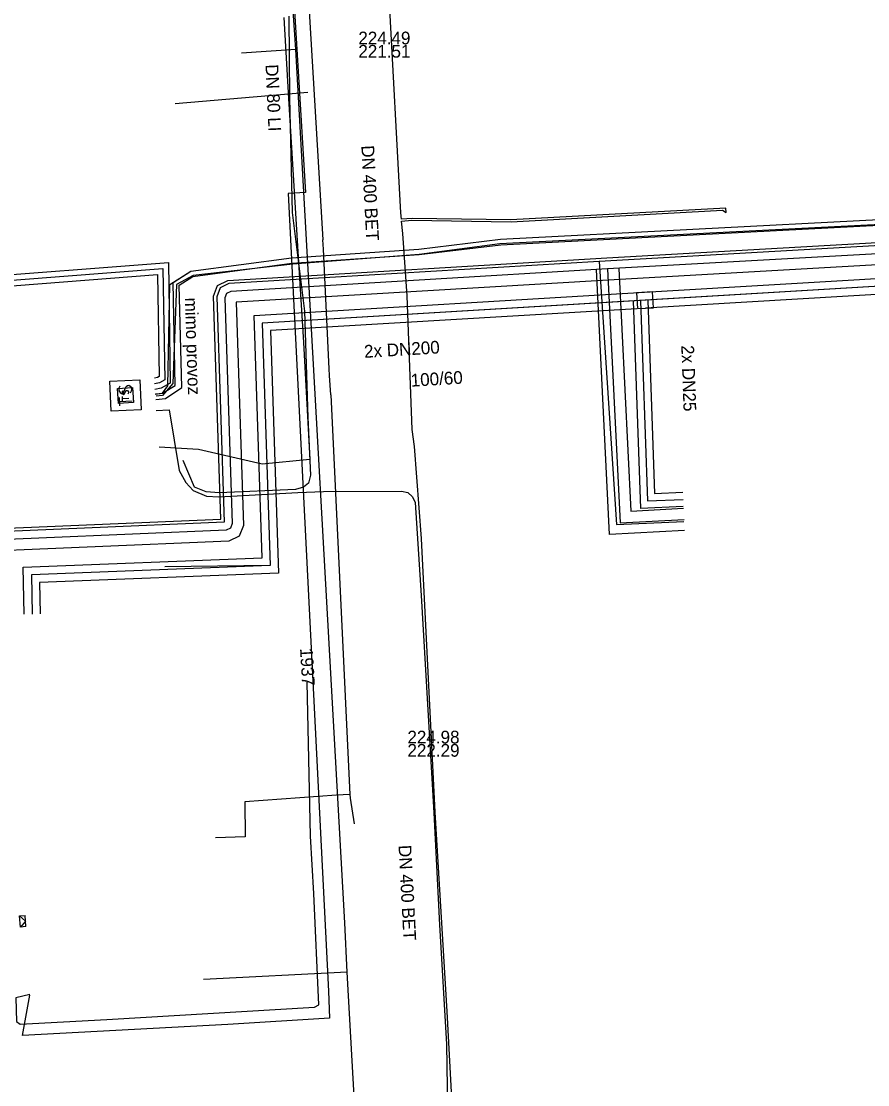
# Model space of a CAD drawing. Extents: x -599951 to -598963, y -1164095 to -1162939.
# Drawn here: x -599392.1 to -599338.9, y -1163110 to -1163043.2 of the extents above; entities that cross this region are included whole.
import ezdxf

# ---------------------------------------------------------------- set-up
doc = ezdxf.new("R2010")
doc.units = 0
for name, color, linetype in [('25', 7, 'Continuous'), ('31', 7, 'Continuous'), ('Vrstva 12', 7, 'Continuous'), ('Vrstva 13', 7, 'Continuous'), ('Vrstva 15', 7, 'Continuous'), ('Vrstva 19', 7, 'Continuous'), ('Vrstva 25', 7, 'Continuous'), ('Vrstva 26', 7, 'Continuous'), ('Vrstva 27', 7, 'Continuous'), ('Vrstva 28', 7, 'Continuous'), ('Vrstva 37', 7, 'Continuous'), ('Vrstva 38', 7, 'Continuous'), ('Vrstva 41', 7, 'Continuous'), ('Vrstva 42', 7, 'Continuous'), ('Vrstva 43', 7, 'Continuous'), ('Vrstva 44', 7, 'Continuous'), ('Vrstva 45', 7, 'Continuous'), ('Vrstva 55', 7, 'Continuous')]:
    doc.layers.add(name, color=color, linetype=linetype)

# ---------------------------------------------------------------- blocks, each defined once
blk = doc.blocks.new('VN640')
at = {"layer": '25'}
for points in [[(-1.89, 1.889), (1.889, 1.889)], [(-1.89, -1.89), (-1.89, 1.889)], [(-1.26, 0.787), (-0.221, 0.787)], [(-0.725, 0.787), (-0.725, -0.788)], [(1.197, 0.661), (0.945, 0.787), (0.661, 0.787), (0.409, 0.661), (0.283, 0.472), (0.283, 0.409), (0.409, 0.22), (1.133, -0.158), (1.259, -0.316), (1.259, -0.473), (1.133, -0.662), (0.913, -0.788), (0.629, -0.788), (0.503, -0.725), (0.283, -0.599)], [(1.889, 1.889), (1.889, -1.89)], [(1.889, -1.89), (-1.89, -1.89)]]:
    blk.add_lwpolyline(points, dxfattribs=at)
blk = doc.blocks.new('NN640')
at = {"layer": '25'}
for points in [[(-1.89, 1.889), (1.889, 1.889)], [(-1.89, -1.89), (-1.89, 1.889)], [(1.889, 1.889), (1.889, -1.89)], [(-1.26, 0.787), (-0.221, 0.787)], [(-0.725, 0.787), (-0.725, -0.788)], [(1.197, 0.661), (0.945, 0.787), (0.661, 0.787), (0.409, 0.661), (0.283, 0.472), (0.283, 0.409), (0.409, 0.22), (1.133, -0.158), (1.259, -0.316), (1.259, -0.473), (1.133, -0.662), (0.913, -0.788), (0.629, -0.788), (0.503, -0.725), (0.283, -0.599)], [(1.889, -1.89), (-1.89, -1.89)]]:
    blk.add_lwpolyline(points, dxfattribs=at)
blk = doc.blocks.new('NN630')
at = {"layer": '31'}
for points in [[(-0.003, -0.7), (-0.703, 0)], [(-0.703, -0.7), (-0.703, 0), (0.697, 0), (0.697, -0.7)], [(-0.003, -0.7), (0.697, 0)], [(-0.703, -0.7), (0.697, -0.7)]]:
    blk.add_lwpolyline(points, dxfattribs=at)

msp = doc.modelspace()

# ---------------------------------------------------------------- linework, layer by layer
at = {"layer": 'Vrstva 12'}
msp.add_line((-599374.11, -1163047.69), (-599382.43, -1163048.4), dxfattribs=at)
for points in [[(-599376.65, -1163014.17), (-599374.24, -1163053.96), (-599375.34, -1163054.02), (-599372.81, -1163104.13), (-599372.73, -1163105.83), (-599379.12, -1163106.22), (-599392.02, -1163106.91), (-599391.55, -1163104.38)], [(-599391.55, -1163104.34), (-599392.43, -1163104.55), (-599392.39, -1163106.03), (-599392.17, -1163106.19), (-599386.73, -1163105.9), (-599373.68, -1163105.12), (-599373.42, -1163104.99), (-599373.72, -1163097.99), (-599373.94, -1163094.39), (-599374.14, -1163084.71)]]:
    msp.add_lwpolyline(points, dxfattribs=at)
at = {"layer": 'Vrstva 13'}
for p, q in [((-599374.86, -1163044.99), (-599378.266, -1163045.218)), ((-599371.633, -1163102.923), (-599380.645, -1163103.401))]:
    msp.add_line(p, q, dxfattribs=at)
msp.add_lwpolyline([(-599370.026, -1163132.931), (-599369.957, -1163132.609), (-599371.633, -1163102.923), (-599371.78, -1163099.83), (-599374.86, -1163044.99), (-599375.586, -1163034.266), (-599375.774, -1163030.889), (-599376.367, -1163018.71), (-599376.476, -1163016.302), (-599376.539, -1163014.958)], dxfattribs=at)
at = {"layer": 'Vrstva 19'}
for points in [[(-599379.168, -1162939.4), (-599379.16, -1162943.1), (-599379.12, -1162943.7), (-599378.94, -1162949.75), (-599378.72, -1162955.7), (-599378.58, -1162957.14), (-599378.39, -1162963.15), (-599378, -1162969.19), (-599377.66, -1162975.24), (-599376.95, -1162984.34), (-599377.05, -1162984.82), (-599377.38, -1162991.49), (-599376.45, -1162998.64), (-599375.963, -1163006.441), (-599375.51, -1163013.7), (-599375.25, -1163017.78), (-599374.71, -1163029.16), (-599374.34, -1163035.46), (-599374.33, -1163035.67), (-599374.09, -1163038.05), (-599374.03, -1163042.23), (-599373.154, -1163056.939)], [(-599372.66, -1163066.68), (-599372.73, -1163065.45), (-599372.751, -1163065.041), (-599373.11, -1163057.53), (-599373.154, -1163056.939)], [(-599372.66, -1163066.68), (-599371.46, -1163091.78), (-599371.45, -1163092), (-599371.19, -1163093.61)], [(-599372.31, -1163091.81), (-599378.06, -1163092.23)], [(-599371.46, -1163091.78), (-599372.31, -1163091.81)], [(-599378.06, -1163092.23), (-599378.04, -1163094.44), (-599379.89, -1163094.5)]]:
    msp.add_lwpolyline(points, dxfattribs=at)
at = {"layer": 'Vrstva 25'}
for points in [[(-599315.215, -1163051.283), (-599334.6, -1163052.28), (-599334.32, -1163059.62), (-599352.922, -1163060.732)], [(-599352.922, -1163060.732), (-599376.96, -1163062.17), (-599376.46, -1163077.4), (-599391.463, -1163077.983), (-599391.409, -1163080.445)], [(-599353.206, -1163060.762), (-599352.762, -1163073.337), (-599350.538, -1163073.244)]]:
    msp.add_lwpolyline(points, dxfattribs=at)
at = {"layer": 'Vrstva 26'}
for points in [[(-599352.952, -1163060.233), (-599334.838, -1163059.15), (-599335.118, -1163051.806), (-599315.733, -1163050.809)], [(-599315.64, -1163051.806), (-599334.082, -1163052.754), (-599333.802, -1163060.09), (-599352.892, -1163061.231)], [(-599391.909, -1163080.456), (-599391.974, -1163077.503), (-599376.976, -1163076.92), (-599377.476, -1163061.7), (-599352.952, -1163060.233)], [(-599350.519, -1163073.694), (-599353.196, -1163073.806), (-599353.656, -1163060.778)], [(-599352.756, -1163060.746), (-599352.328, -1163072.868), (-599350.557, -1163072.794)], [(-599353.439, -1163061.264), (-599376.444, -1163062.64), (-599375.944, -1163077.88), (-599390.952, -1163078.464), (-599390.909, -1163080.434)]]:
    msp.add_lwpolyline(points, dxfattribs=at)
at = {"layer": 'Vrstva 27'}
msp.add_lwpolyline([(-599353.391, -1163061.261), (-599352.393, -1163061.201), (-599352.453, -1163060.203), (-599353.451, -1163060.263)], close=True, dxfattribs=at)
at = {"layer": 'Vrstva 37'}
for points in [[(-599290.485, -1162978.048), (-599290.017, -1162984.479), (-599289.156, -1163008.706), (-599316.634, -1163010.66), (-599315.123, -1163051.266), (-599334.6, -1163052.28), (-599334.32, -1163059.62), (-599376.96, -1163062.17), (-599376.46, -1163077.4), (-599383.092, -1163077.483)], [(-599317.187, -1163048.75), (-599336.512, -1163049.77), (-599337.062, -1163050.029), (-599337.271, -1163050.599), (-599337.045, -1163057.239), (-599355.804, -1163058.295), (-599379.07, -1163059.686), (-599379.613, -1163059.945), (-599379.821, -1163060.51), (-599379.356, -1163074.675), (-599396.927, -1163075.422)], [(-599317.355, -1163049.26), (-599336.388, -1163050.264), (-599336.663, -1163050.394), (-599336.767, -1163050.679), (-599336.517, -1163057.25), (-599336.62, -1163057.534), (-599336.807, -1163057.727), (-599355.275, -1163058.764)], [(-599355.804, -1163058.295), (-599354.708, -1163074.818), (-599350.484, -1163074.635)], [(-599355.275, -1163058.764), (-599378.943, -1163060.179), (-599379.214, -1163060.309), (-599379.318, -1163060.591), (-599378.853, -1163074.758), (-599378.959, -1163075.043), (-599379.235, -1163075.17), (-599396.906, -1163075.921)], [(-599355.275, -1163058.764), (-599354.489, -1163074.709), (-599350.473, -1163074.496)], [(-599353.206, -1163060.762), (-599352.762, -1163073.337), (-599350.538, -1163073.244)]]:
    msp.add_lwpolyline(points, dxfattribs=at)
at = {"layer": 'Vrstva 38'}
for points in [[(-599355.314, -1163058.065), (-599337.225, -1163057.049), (-599337.472, -1163050.568), (-599337.221, -1163049.883), (-599336.562, -1163049.572), (-599318.079, -1163048.597)], [(-599318.029, -1163049.996), (-599336.056, -1163050.948), (-599335.812, -1163057.361), (-599336.014, -1163057.915), (-599336.496, -1163058.41), (-599355.236, -1163059.463)], [(-599396.936, -1163075.222), (-599379.562, -1163074.484), (-599380.023, -1163060.478), (-599379.773, -1163059.8), (-599379.121, -1163059.488), (-599355.317, -1163058.065)], [(-599350.435, -1163075.195), (-599355.153, -1163075.445), (-599355.974, -1163058.799)], [(-599354.576, -1163058.73), (-599353.824, -1163073.973), (-599350.51, -1163073.797)], [(-599355.233, -1163059.463), (-599378.609, -1163060.86), (-599378.148, -1163074.873), (-599378.404, -1163075.557), (-599379.067, -1163075.864), (-599396.876, -1163076.621)]]:
    msp.add_lwpolyline(points, dxfattribs=at)
at = {"layer": 'Vrstva 42'}
for points in [[(-599290.485, -1162978.048), (-599290.017, -1162984.479), (-599289.156, -1163008.706), (-599316.634, -1163010.66), (-599315.123, -1163051.266), (-599334.6, -1163052.28), (-599334.32, -1163059.62), (-599376.96, -1163062.17), (-599376.46, -1163077.4), (-599383.092, -1163077.483)], [(-599383.651, -1163066.976), (-599383.04, -1163066.909), (-599382.022, -1163066.204), (-599382.174, -1163059.783), (-599381.318, -1163059.25), (-599375.097, -1163058.41), (-599367.103, -1163057.865), (-599361.976, -1163057.256), (-599337.823, -1163055.997), (-599331.491, -1163055.747), (-599327.851, -1163055.894), (-599326.518, -1163055.909), (-599325.108, -1163055.298), (-599317.982, -1163054.797), (-599317.726, -1163053.681), (-599317.998, -1163048.198), (-599318.101, -1163046.358), (-599319.737, -1163013.607), (-599313.234, -1163013.647), (-599302.452, -1163013.142), (-599302.43, -1163013.302)], [(-599383.689, -1163066.628), (-599383.231, -1163066.578), (-599382.434, -1163066.081), (-599382.551, -1163059.616), (-599381.439, -1163058.913), (-599375.132, -1163058.062), (-599367.136, -1163057.516), (-599362.006, -1163056.907), (-599337.839, -1163055.647), (-599331.491, -1163055.397), (-599327.842, -1163055.544), (-599326.589, -1163055.558), (-599325.634, -1163055.144), (-599325.807, -1163048.071), (-599326.049, -1163031.305), (-599325.925, -1163029.401), (-599326.626, -1163029.416)], [(-599375.606, -1163042.967), (-599375.312, -1163048.07), (-599374.757, -1163057.341), (-599374.368, -1163063.397), (-599373.979, -1163070.727), (-599376.978, -1163071.028), (-599380.957, -1163070.115), (-599383.43, -1163069.96)], [(-599375.3, -1163042.9), (-599375.25, -1163048.03), (-599375.09, -1163055.23), (-599374.31, -1163061.42), (-599374.1, -1163068.1), (-599373.94, -1163071.72), (-599374.05, -1163072.22), (-599374.38, -1163072.47), (-599374.88, -1163072.61), (-599379.67, -1163072.83), (-599380.49, -1163072.76), (-599381.22, -1163072.48), (-599381.929, -1163070.806)], [(-599317.187, -1163048.75), (-599336.512, -1163049.77), (-599337.062, -1163050.029), (-599337.271, -1163050.599), (-599337.045, -1163057.239), (-599355.804, -1163058.295), (-599379.07, -1163059.686), (-599379.613, -1163059.945), (-599379.821, -1163060.51), (-599379.356, -1163074.675), (-599396.927, -1163075.422)], [(-599396.679, -1163063.46), (-599395.958, -1163059.371), (-599382.86, -1163058.357), (-599382.738, -1163065.936), (-599383.303, -1163066.256), (-599383.715, -1163066.337)], [(-599355.804, -1163058.295), (-599354.708, -1163074.818), (-599350.484, -1163074.635)], [(-599396.613, -1163065.093), (-599395.661, -1163059.699), (-599383.204, -1163058.734), (-599383.092, -1163065.734), (-599383.426, -1163065.924), (-599383.731, -1163065.983)], [(-599396.114, -1163064.281), (-599395.363, -1163060.027), (-599383.548, -1163059.112), (-599383.445, -1163065.532), (-599383.549, -1163065.591), (-599383.733, -1163065.627)], [(-599353.206, -1163060.762), (-599352.762, -1163073.337), (-599350.538, -1163073.244)], [(-599383.619, -1163067.656), (-599382.807, -1163067.626), (-599382.182, -1163071.419)], [(-599382.182, -1163071.419), (-599381.77, -1163072.17), (-599381.31, -1163072.691), (-599380.46, -1163073.03), (-599379.7, -1163073.08), (-599374.727, -1163072.805), (-599373.12, -1163072.75), (-599368.22, -1163072.72), (-599367.82, -1163072.81), (-599367.53, -1163073.08), (-599367.37, -1163073.44), (-599366.98, -1163079.28), (-599366.18, -1163092.92), (-599365.83, -1163099.96), (-599365.4, -1163107.45), (-599365.303, -1163112.901)]]:
    msp.add_lwpolyline(points, dxfattribs=at)
at = {"layer": 'Vrstva 44'}
for points in [[(-599319.852, -1163013.162), (-599318.18, -1163046.456), (-599318.084, -1163048.366), (-599317.839, -1163053.69), (-599318.246, -1163054.791), (-599325.245, -1163055.207), (-599325.89, -1163055.475), (-599326.61, -1163055.773), (-599327.798, -1163055.76), (-599331.487, -1163055.646), (-599337.722, -1163055.948), (-599362.048, -1163057.195), (-599367.114, -1163057.869), (-599375.04, -1163058.472), (-599381.305, -1163059.176), (-599382.343, -1163059.738), (-599382.569, -1163065.956), (-599383.104, -1163066.565), (-599383.23, -1163066.711), (-599383.624, -1163066.757)], [(-599383.673, -1163066.61), (-599383.231, -1163066.578), (-599382.894, -1163066.117), (-599382.776, -1163059.746), (-599381.439, -1163058.913), (-599375.132, -1163058.062), (-599367.136, -1163057.516), (-599362.006, -1163056.907), (-599337.839, -1163055.647), (-599331.491, -1163055.397), (-599327.842, -1163055.544), (-599326.589, -1163055.558), (-599325.192, -1163054.953), (-599318.265, -1163054.466), (-599318.078, -1163053.65), (-599318.348, -1163048.216), (-599318.451, -1163046.377), (-599319.866, -1163018.049)]]:
    msp.add_lwpolyline(points, dxfattribs=at)
at = {"layer": 'Vrstva 55'}
msp.add_lwpolyline([(-599364.74, -1163116.68), (-599365.35, -1163105.4), (-599366.1, -1163092.88), (-599366.97, -1163075.69), (-599367.41, -1163069.92), (-599367.55, -1163068.86), (-599367.87, -1163060.45), (-599368.14, -1163056.55), (-599368.212, -1163055.765), (-599367.56, -1163055.71), (-599361.34, -1163055.8), (-599348.049, -1163055.082), (-599347.82, -1163055.23), (-599347.85, -1163054.94), (-599361.36, -1163055.69), (-599367.55, -1163055.6), (-599368.224, -1163055.632), (-599368.26, -1163055.24), (-599368.99, -1163041.65)], dxfattribs=at)

# ---------------------------------------------------------------- block references
at = {"layer": 'Vrstva 43'}
for name, p, xscale, yscale, rotation in [('NN640', (-599385.552, -1163066.716), 0.5000000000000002, 0.4999999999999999, 93), ('NN630', (-599392.176, -1163099.748), 0.5, 0.5000000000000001, 94)]:
    msp.add_blockref(name, p, dxfattribs=dict(at, xscale=xscale, yscale=yscale, rotation=rotation))
at = {"layer": 'Vrstva 45', "xscale": 0.2500000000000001, "yscale": 0.25, "rotation": 93}
msp.add_blockref('VN640', (-599385.552, -1163066.716), dxfattribs=at)

# ---------------------------------------------------------------- texts
at = {"layer": 'Vrstva 12'}
for s, p in [('224.49', (-599370.929, -1163044.664)), ('221.51', (-599370.929, -1163045.496)), ('224.98', (-599367.845, -1163088.57)), ('222.29', (-599367.845, -1163089.402))]:
    msp.add_text(s, height=0.8, dxfattribs=at).set_placement(p)
for p in [(-599370.742, -1163051.023), (-599368.407, -1163094.965)]:
    msp.add_text('DN 400 BET', height=0.8, rotation=273.01439, dxfattribs=at).set_placement(p)
at = {"layer": 'Vrstva 15'}
for s, rotation, p in [('DN 80 LI', 272.59177, (-599376.76, -1163045.933)), ('1937', 273.21455, (-599374.591, -1163082.599))]:
    msp.add_text(s, height=0.8, rotation=rotation, dxfattribs=at).set_placement(p)
at = {"layer": 'Vrstva 28'}
for s, rotation, p in [('2x DN200', 3.42347, (-599370.545, -1163064.353)), ('2x DN25', 272.02217, (-599350.648, -1163063.568)), ('100/60', 3.42347, (-599367.615, -1163066.164))]:
    msp.add_text(s, height=0.8, rotation=rotation, dxfattribs=at).set_placement(p)
at = {"layer": 'Vrstva 41'}
msp.add_text('mimo provoz', height=0.8, rotation=271.88331, dxfattribs=at).set_placement((-599381.824, -1163060.578))

doc.saveas('drawing.dxf')
